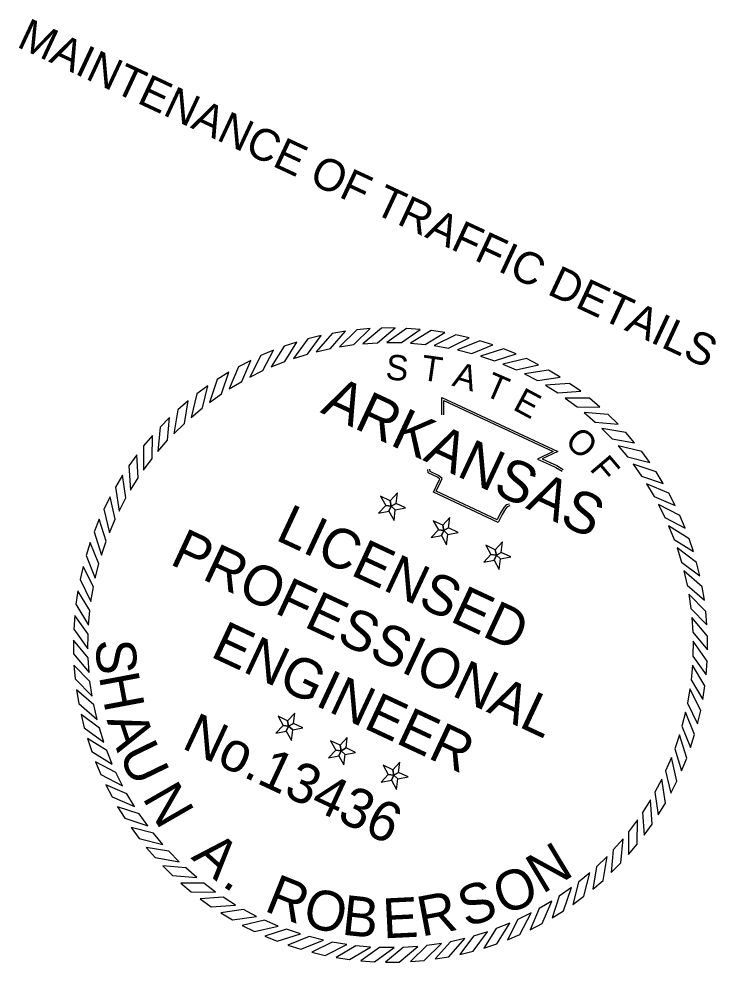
# Model space of a CAD drawing. Extents: x 980546 to 982069, y 1837601 to 1838871.
# Drawn here: x 981937.7 to 982068.9, y 1838373 to 1838550.4 of the extents above; entities that cross this region are included whole.
import ezdxf

# ---------------------------------------------------------------- set-up
doc = ezdxf.new("R2010")
doc.units = 0
doc.layers.add('G-ANNO-SYMB', color=7, linetype='Continuous')
doc.layers.add('G-ANNO-TEXT', color=7, linetype='Continuous')

msp = doc.modelspace()

# ---------------------------------------------------------------- linework, layer by layer
at = {"layer": 'G-ANNO-SYMB'}
for points in [[(981999.15, 1838491.68), (981996.62, 1838491.27), (981993.62, 1838487.82), (981996.33, 1838488.43)], [(982003.81, 1838492.16), (982001.26, 1838491.95), (981998, 1838488.74), (982000.74, 1838489.14)], [(982008.5, 1838492.28), (982005.93, 1838492.26), (982002.43, 1838489.32), (982005.19, 1838489.51)], [(982013.18, 1838492.02), (982010.62, 1838492.21), (982006.89, 1838489.55), (982009.66, 1838489.52)], [(982017.82, 1838491.4), (982015.28, 1838491.79), (982011.36, 1838489.43), (982014.12, 1838489.18)], [(981994.55, 1838490.84), (981992.06, 1838490.22), (981989.34, 1838486.55), (981991.98, 1838487.37)], [(982022.4, 1838490.42), (982019.9, 1838491), (982015.81, 1838488.96), (982018.54, 1838488.5)], [(982026.89, 1838489.08), (982024.44, 1838489.86), (982020.2, 1838488.15), (982022.89, 1838487.47)], [(981985.6, 1838488.08), (981983.24, 1838487.08), (981981.13, 1838483.03), (981983.61, 1838484.26)], [(981990.02, 1838489.64), (981987.59, 1838488.83), (981985.16, 1838484.95), (981987.74, 1838485.98)], [(982031.26, 1838487.39), (982028.88, 1838488.36), (982024.52, 1838486.99), (982027.15, 1838486.1)], [(981981.32, 1838486.18), (981979.04, 1838485), (981977.25, 1838480.8), (981979.63, 1838482.22)], [(982035.48, 1838485.37), (982033.19, 1838486.52), (982028.73, 1838485.49), (982031.28, 1838484.4)], [(981977.2, 1838483.96), (981975.02, 1838482.6), (981973.57, 1838478.27), (981975.83, 1838479.87)], [(982039.53, 1838483.02), (982037.34, 1838484.35), (982032.82, 1838483.67), (982035.27, 1838482.38)], [(981973.26, 1838481.41), (981971.2, 1838479.89), (981970.09, 1838475.46), (981972.22, 1838477.23)], [(982043.39, 1838480.36), (982041.3, 1838481.85), (982036.74, 1838481.53), (982039.09, 1838480.06)], [(982047.02, 1838477.4), (982045.06, 1838479.06), (982040.49, 1838479.1), (982042.71, 1838477.44)], [(981969.54, 1838478.57), (981967.6, 1838476.89), (981966.85, 1838472.38), (981968.83, 1838474.32)], [(982050.42, 1838474.17), (982048.59, 1838475.97), (982044.03, 1838476.37), (982046.12, 1838474.55)], [(981966.05, 1838475.44), (981964.25, 1838473.62), (981963.85, 1838469.06), (981965.68, 1838471.15)], [(981962.82, 1838472.05), (981961.17, 1838470.09), (981961.13, 1838465.52), (981962.78, 1838467.74)], [(982053.54, 1838470.68), (982051.86, 1838472.62), (982047.35, 1838473.38), (982049.29, 1838471.4)], [(981959.87, 1838468.41), (981958.37, 1838466.33), (981958.69, 1838461.77), (981960.17, 1838464.11)], [(982056.39, 1838466.96), (982054.87, 1838469.03), (982050.43, 1838470.13), (982052.2, 1838468.01)], [(982058.93, 1838463.03), (982057.58, 1838465.21), (982053.24, 1838466.66), (982054.84, 1838464.4)], [(981957.21, 1838464.56), (981955.88, 1838462.36), (981956.56, 1838457.84), (981957.84, 1838460.3)], [(982061.16, 1838458.91), (982059.98, 1838461.19), (982055.77, 1838462.97), (982057.19, 1838460.59)], [(981954.86, 1838460.51), (981953.71, 1838458.21), (981954.74, 1838453.76), (981955.83, 1838456.31)], [(982007.75, 1838458.77), (982007.55, 1838459.79), (982005.76, 1838460.63), (982006.72, 1838458.89)], [(982007.75, 1838458.77), (982008.66, 1838459.27), (982008.91, 1838461.24), (982007.55, 1838459.79)], [(982007.75, 1838458.77), (982006.72, 1838458.89), (982005.37, 1838457.44), (982007.31, 1838457.82)], [(982007.75, 1838458.77), (982007.31, 1838457.82), (982008.27, 1838456.09), (982008.51, 1838458.06)], [(982007.75, 1838458.77), (982008.51, 1838458.06), (982010.46, 1838458.43), (982008.66, 1838459.27)], [(982063.06, 1838454.62), (982062.06, 1838456.99), (982058, 1838459.1), (982059.23, 1838456.62)], [(981952.83, 1838456.28), (981951.86, 1838453.91), (981953.24, 1838449.55), (981954.13, 1838452.17)], [(982017.64, 1838454.16), (982017.44, 1838455.18), (982015.65, 1838456.02), (982016.61, 1838454.28)], [(982017.64, 1838454.16), (982018.55, 1838454.66), (982018.79, 1838456.63), (982017.44, 1838455.18)], [(982017.64, 1838454.16), (982016.61, 1838454.28), (982015.25, 1838452.83), (982017.2, 1838453.21)], [(982017.64, 1838454.16), (982018.4, 1838453.45), (982020.35, 1838453.82), (982018.55, 1838454.66)], [(982064.61, 1838450.21), (982063.8, 1838452.64), (982059.92, 1838455.06), (982060.95, 1838452.49)], [(982017.64, 1838454.16), (982017.2, 1838453.21), (982018.16, 1838451.48), (982018.4, 1838453.45)], [(981951.14, 1838451.91), (981950.37, 1838449.47), (981952.08, 1838445.23), (981952.76, 1838447.92)], [(982027.53, 1838449.55), (982027.33, 1838450.57), (982025.53, 1838451.41), (982026.49, 1838449.67)], [(982027.53, 1838449.55), (982028.44, 1838450.05), (982028.68, 1838452.02), (982027.33, 1838450.57)], [(982065.81, 1838445.68), (982065.2, 1838448.17), (982061.52, 1838450.89), (982062.35, 1838448.24)], [(982027.53, 1838449.55), (982026.49, 1838449.67), (982025.14, 1838448.22), (982027.09, 1838448.6)], [(982027.53, 1838449.55), (982027.09, 1838448.6), (982028.05, 1838446.87), (982028.29, 1838448.84)], [(982027.53, 1838449.55), (982028.29, 1838448.84), (982030.23, 1838449.21), (982028.44, 1838450.05)], [(981949.8, 1838447.42), (981949.22, 1838444.93), (981951.26, 1838440.83), (981951.73, 1838443.57)], [(982066.66, 1838441.07), (982066.24, 1838443.6), (982062.79, 1838446.6), (982063.4, 1838443.9)], [(981948.82, 1838442.84), (981948.44, 1838440.31), (981950.79, 1838436.39), (981951.04, 1838439.15)], [(982067.14, 1838436.41), (982066.92, 1838438.97), (982063.72, 1838442.23), (982064.12, 1838439.49)], [(981948.2, 1838438.2), (981948.02, 1838435.64), (981950.67, 1838431.92), (981950.71, 1838434.69)], [(982067.25, 1838431.73), (982067.24, 1838434.29), (982064.3, 1838437.8), (982064.48, 1838435.03)], [(981947.95, 1838433.52), (981947.96, 1838430.96), (981950.9, 1838427.46), (981950.72, 1838430.22)], [(982067, 1838427.05), (982067.18, 1838429.61), (982064.53, 1838433.33), (982064.49, 1838430.56)], [(981948.06, 1838428.84), (981948.28, 1838426.28), (981951.48, 1838423.02), (981951.08, 1838425.77)], [(982066.38, 1838422.41), (982066.76, 1838424.94), (982064.41, 1838428.86), (982064.16, 1838426.1)], [(981948.54, 1838424.18), (981948.96, 1838421.65), (981952.41, 1838418.65), (981951.79, 1838421.35)], [(982065.39, 1838417.83), (982065.98, 1838420.33), (982063.94, 1838424.42), (982063.47, 1838421.69)], [(981949.39, 1838419.57), (981950, 1838417.08), (981953.68, 1838414.36), (981952.85, 1838417.01)], [(981988.45, 1838417.36), (981988.25, 1838418.39), (981986.45, 1838419.22), (981987.41, 1838417.49)], [(981988.45, 1838417.36), (981989.36, 1838417.87), (981989.6, 1838419.84), (981988.25, 1838418.39)], [(982064.06, 1838413.34), (982064.83, 1838415.78), (982063.12, 1838420.02), (982062.44, 1838417.34)], [(981988.45, 1838417.36), (981987.41, 1838417.49), (981986.06, 1838416.04), (981988.01, 1838416.42)], [(981988.45, 1838417.36), (981988.01, 1838416.42), (981988.97, 1838414.69), (981989.21, 1838416.65)], [(981988.45, 1838417.36), (981989.21, 1838416.65), (981991.15, 1838417.03), (981989.36, 1838417.87)], [(981998.33, 1838412.75), (981999.24, 1838413.26), (981999.49, 1838415.23), (981998.13, 1838413.78)], [(982062.37, 1838408.97), (982063.33, 1838411.34), (982061.96, 1838415.71), (982061.07, 1838413.08)], [(981950.59, 1838415.05), (981951.4, 1838412.61), (981955.28, 1838410.19), (981954.25, 1838412.76)], [(981998.33, 1838412.75), (981998.13, 1838413.78), (981996.34, 1838414.61), (981997.3, 1838412.88)], [(981998.33, 1838412.75), (981997.3, 1838412.88), (981995.95, 1838411.43), (981997.89, 1838411.81)], [(981998.33, 1838412.75), (981997.89, 1838411.81), (981998.85, 1838410.08), (981999.1, 1838412.04)], [(981998.33, 1838412.75), (981999.1, 1838412.04), (982001.04, 1838412.42), (981999.24, 1838413.26)], [(981952.14, 1838410.63), (981953.14, 1838408.26), (981957.2, 1838406.15), (981955.97, 1838408.64)], [(982008.22, 1838408.14), (982008.02, 1838409.17), (982006.23, 1838410), (982007.19, 1838408.27)], [(982008.22, 1838408.14), (982009.13, 1838408.65), (982009.37, 1838410.62), (982008.02, 1838409.17)], [(982060.34, 1838404.74), (982061.49, 1838407.04), (982060.46, 1838411.49), (982059.37, 1838408.94)], [(982008.22, 1838408.14), (982007.19, 1838408.27), (982005.84, 1838406.82), (982007.78, 1838407.2)], [(982008.22, 1838408.14), (982007.78, 1838407.2), (982008.74, 1838405.47), (982008.98, 1838407.43)], [(982008.22, 1838408.14), (982008.98, 1838407.43), (982010.93, 1838407.81), (982009.13, 1838408.65)], [(981954.04, 1838406.34), (981955.22, 1838404.07), (981959.43, 1838402.28), (981958.01, 1838404.66)], [(982057.99, 1838400.69), (982059.32, 1838402.89), (982058.64, 1838407.41), (982057.36, 1838404.96)], [(982055.33, 1838396.84), (982056.83, 1838398.92), (982056.51, 1838403.48), (982055.03, 1838401.14)], [(981956.27, 1838402.22), (981957.62, 1838400.04), (981961.96, 1838398.59), (981960.36, 1838400.85)], [(982052.38, 1838393.2), (982054.03, 1838395.16), (982054.07, 1838399.74), (982052.41, 1838397.51)], [(981958.81, 1838398.29), (981960.33, 1838396.22), (981964.77, 1838395.12), (981963, 1838397.25)], [(982049.15, 1838389.81), (982050.95, 1838391.64), (982051.35, 1838396.19), (982049.52, 1838394.11)], [(981961.66, 1838394.57), (981963.34, 1838392.63), (981967.85, 1838391.87), (981965.91, 1838393.86)], [(982045.66, 1838386.68), (982047.6, 1838388.36), (982048.35, 1838392.87), (982046.37, 1838390.93)], [(981964.78, 1838391.08), (981966.61, 1838389.28), (981971.17, 1838388.88), (981969.08, 1838390.7)], [(982041.94, 1838383.84), (982044, 1838385.36), (982045.11, 1838389.8), (982042.98, 1838388.02)], [(981968.18, 1838387.85), (981970.14, 1838386.19), (981974.71, 1838386.16), (981972.49, 1838387.81)], [(982038, 1838381.29), (982040.18, 1838382.65), (982041.63, 1838386.99), (982039.37, 1838385.38)], [(981971.81, 1838384.89), (981973.9, 1838383.4), (981978.46, 1838383.72), (981976.11, 1838385.19)], [(982033.88, 1838379.07), (982036.16, 1838380.25), (982037.95, 1838384.46), (982035.57, 1838383.04)], [(981975.67, 1838382.23), (981977.86, 1838380.91), (981982.38, 1838381.58), (981979.93, 1838382.87)], [(982029.6, 1838377.17), (982031.96, 1838378.17), (982034.07, 1838382.22), (982031.59, 1838380.99)], [(981979.72, 1838379.88), (981982.01, 1838378.73), (981986.47, 1838379.76), (981983.92, 1838380.85)], [(982025.18, 1838375.62), (982027.61, 1838376.42), (982030.04, 1838380.3), (982027.46, 1838379.27)], [(981983.94, 1838377.86), (981986.32, 1838376.89), (981990.68, 1838378.27), (981988.05, 1838379.15)], [(982020.65, 1838374.41), (982023.14, 1838375.03), (982025.86, 1838378.7), (982023.22, 1838377.88)], [(981988.31, 1838376.17), (981990.76, 1838375.39), (981995, 1838377.11), (981992.31, 1838377.79)], [(981992.8, 1838374.83), (981995.3, 1838374.25), (981999.39, 1838376.29), (981996.66, 1838376.75)], [(982011.38, 1838373.09), (982013.94, 1838373.3), (982017.2, 1838376.51), (982014.46, 1838376.11)], [(982016.04, 1838373.57), (982018.58, 1838373.98), (982021.58, 1838377.44), (982018.87, 1838376.82)], [(981997.38, 1838373.85), (981999.92, 1838373.46), (982003.84, 1838375.82), (982001.08, 1838376.07)], [(982002.02, 1838373.23), (982004.58, 1838373.04), (982008.31, 1838375.7), (982005.53, 1838375.73)], [(982006.7, 1838372.97), (982009.27, 1838372.99), (982012.77, 1838375.93), (982010, 1838375.74)]]:
    msp.add_lwpolyline(points, close=True, dxfattribs=at)
for points in [[(982017.24, 1838475.91), (982017.25, 1838479.23), (982039.06, 1838469.07), (982036.17, 1838467.63), (982037.66, 1838466.96), (982038.91, 1838466.4), (982040.08, 1838465.68)], [(982017.62, 1838475.91), (982017.63, 1838478.63), (982038.19, 1838469.06), (982035.29, 1838467.61), (982037.51, 1838466.61), (982038.73, 1838466.06), (982039.89, 1838465.36)], [(982030.09, 1838458.79), (982029.57, 1838458.66), (982029.24, 1838458.27), (982028.59, 1838457.19), (982027.89, 1838455.68), (982015.71, 1838461.36), (982016.66, 1838463.4), (982016.87, 1838463.85), (982016.45, 1838464.23), (982014.72, 1838465.04), (982014.63, 1838465.65)], [(982029.99, 1838459.16), (982029.36, 1838459), (982028.93, 1838458.49), (982028.25, 1838457.37), (982027.7, 1838456.19), (982016.22, 1838461.55), (982017.01, 1838463.24), (982017.34, 1838463.94), (982016.66, 1838464.55), (982015.06, 1838465.3), (982015, 1838465.71)]]:
    msp.add_lwpolyline(points, dxfattribs=at)

# ---------------------------------------------------------------- texts
for s, height, rotation, p in [('S', 4.75, 354.7726, (982006.55, 1838482.64)), ('T', 4.75, 351.9015, (982013.16, 1838482.54)), ('A', 4.75, 343.6788, (982019.02, 1838481.47)), ('T', 4.75, 336.4789, (982024.97, 1838479.73)), ('ARKANSAS', 7.747, 335, (981994.25, 1838476.45)), ('E', 4.75, 331.672, (982030.42, 1838477.04)), ('O', 4.75, 316.2218, (982040.18, 1838470.69)), ('F', 4.75, 310.3628, (982044.92, 1838465.72)), ('LICENSED', 7.5, 335, (981985.74, 1838452.52)), ('PROFESSIONAL', 7.5, 335, (981965.88, 1838447.94)), ('ENGINEER', 7.5, 335, (981973.52, 1838430.54)), ('S', 7.5, 273.1636, (981952.12, 1838433.56)), ('H', 7.5, 280.619, (981952.73, 1838426.79)), ('No.13436', 7.47, 335, (981968.11, 1838413.33)), ('A', 7.5, 288.4472, (981954.16, 1838418.57)), ('U', 7.5, 295.9026, (981956.33, 1838412.17)), ('N', 7.5, 299.9326, (981960.82, 1838403.91)), ('A', 7.5, 318.0991, (981969.94, 1838392.55)), ('N', 7.5, 31.1007, (982036.19, 1838385.71)), ('O', 7.5, 19.7757, (982028.62, 1838381.79)), ('R', 7.5, 338.2287, (981983.64, 1838382.71)), ('.', 7.5, 326.3, (981975.7, 1838387.46)), ('S', 7.5, 18.4878, (982021.84, 1838379.46)), ('O', 7.5, 346.4296, (981990.8, 1838379.91)), ('B', 7.5, 353.885, (981998.28, 1838378.17)), ('E', 7.5, 2.8315, (982006.29, 1838377.43)), ('R', 7.5, 10.6597, (982013.44, 1838377.76))]:
    msp.add_text(s, height=height, rotation=rotation, dxfattribs=at).set_placement(p)
at = {"layer": 'G-ANNO-TEXT'}
msp.add_text('MAINTENANCE OF TRAFFIC DETAILS', height=6, rotation=335, dxfattribs=at).set_placement((981937.1, 1838545.27))

doc.saveas('drawing.dxf')
